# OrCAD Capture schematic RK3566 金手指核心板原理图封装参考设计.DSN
size A2; title: 野火_EBF RK3566 核心板; rev: V1.0; note: Connector; note: https://yehuosm.tmall.com
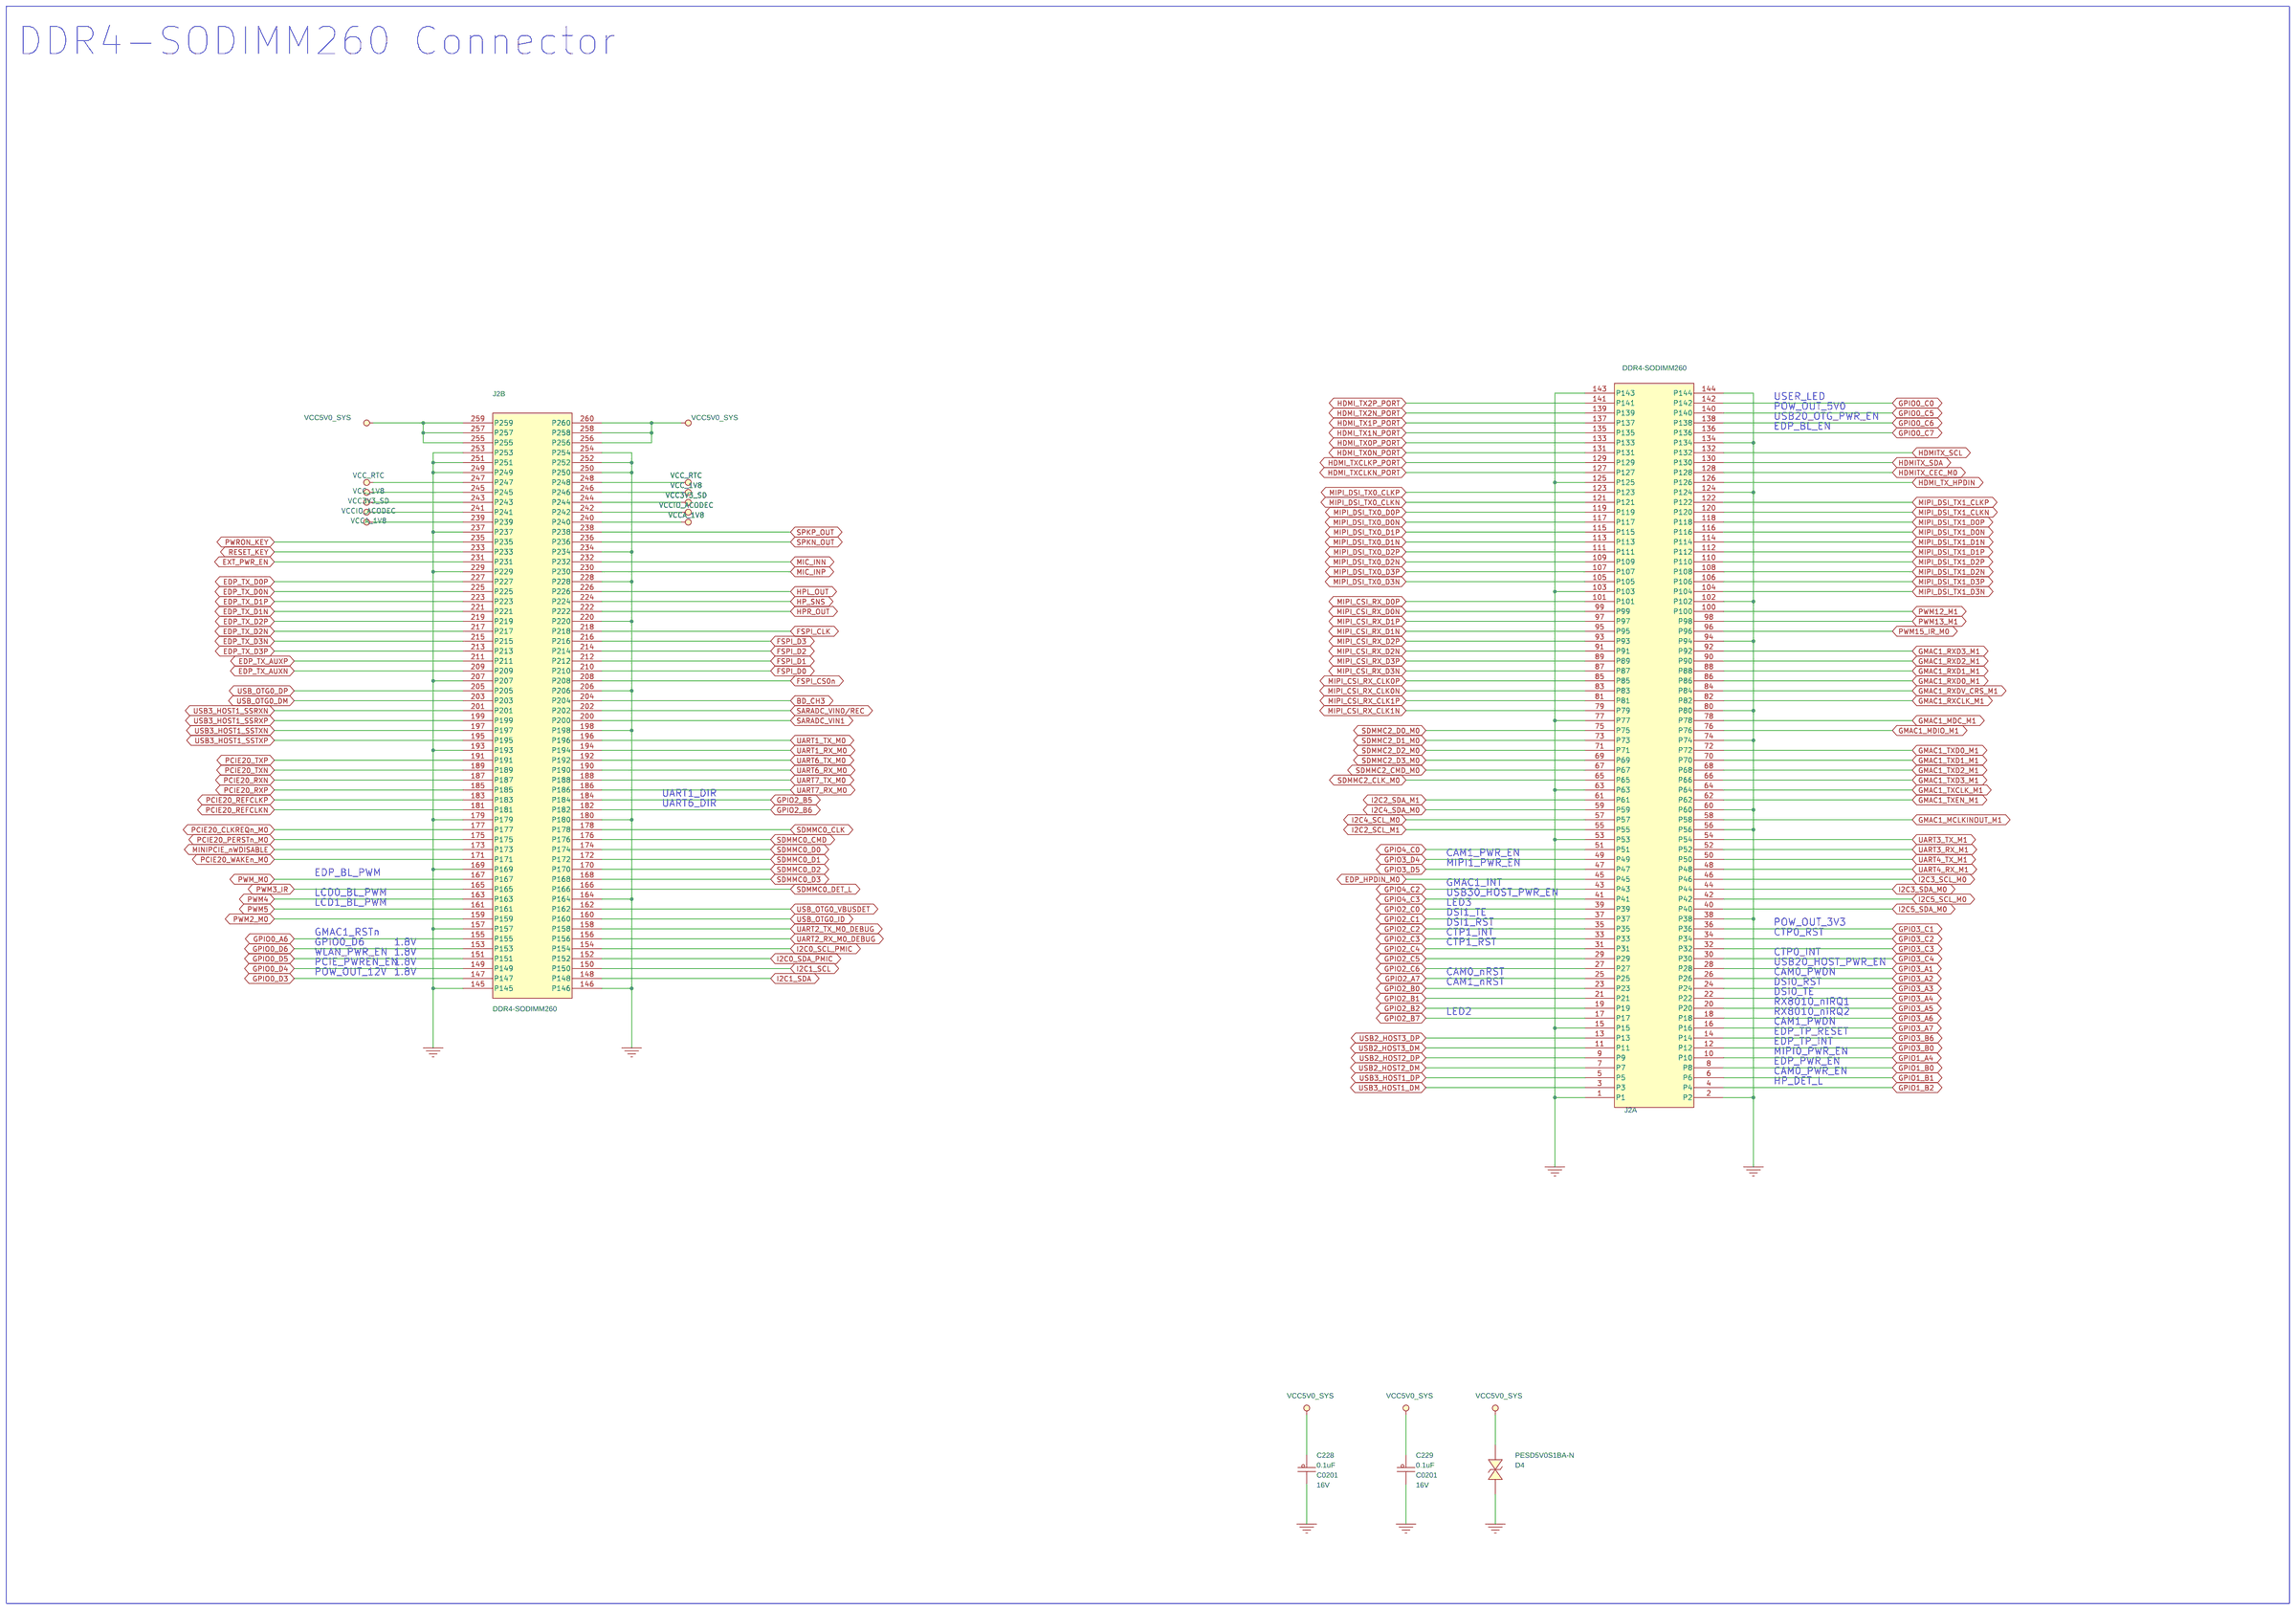
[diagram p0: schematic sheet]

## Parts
C228  0.1uF  [C0201]
C229  0.1uF  [C0201]
D4  PESD5V0S1BA-N  [sod323_CA]
J2  DDR4-SODIMM260  [SODIMMDDR4_260_0p5]  (sections A,B)

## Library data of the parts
C228 C229 = CAP_NP: Voltage: 16V; 规格: 贴片电容0.1uF 10% 16V X5R 0201; 规格编号: CL03A104KO3NNNC; 规格书: 三星电容.pdf; 价格: 0.006; 类别: 贴片电容0201; 品牌: 三星; 生命周期: 量产; 条码: EBF29060189
D4 = DIODE_BI-DIR_TRIG: 规格: 防静电保护ESD二极管 箝位电压21V 击穿电压6V 反向关断电压5V; 规格书: 伯恩半导体-PESD5V0S1BA-N.pdf; 价格: 0.196644; 类别: 贴片ESD; 品牌: 伯恩半导体; 生命周期: 量产; 条码: EBF29140021
J2 = DDR4-SODIMM260: 规格: 正装 DDR4 笔记本内存条 金手指 板框 260pin 间距0.5mm; 类别: 金手指连接器; 生命周期: 量产; 条码: EBF29040118

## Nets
GND: C228.2 C229.2 D4.1 J2.1(P1) J2.2(P2) J2.15(P15) J2.38(P38) J2.53(P53) J2.56(P56) J2.60(P60) J2.63(P63) J2.74(P74) J2.77(P77) J2.80(P80) J2.94(P94) J2.102(P102) J2.103(P103) J2.124(P124) J2.125(P125) J2.134(P134) J2.143(P143) J2.144(P144) J2.145(P145) J2.146(P146) J2.157(P157) J2.164(P164) J2.169(P169) J2.179(P179) J2.180(P180) J2.193(P193) J2.198(P198) J2.206(P206) J2.207(P207) J2.220(P220) J2.228(P228) J2.229(P229) J2.234(P234) J2.237(P237) J2.249(P249) J2.250(P250) J2.251(P251) J2.252(P252) J2.253(P253) J2.254(P254)
VCC3V3_SD: J2.243(P243) J2.244(P244)
VCC5V0_SYS: C228.1 C229.1 D4.2 J2.255(P255) J2.256(P256) J2.257(P257) J2.258(P258) J2.259(P259) J2.260(P260)
VCC_1V8: J2.245(P245) J2.246(P246)
VCC_RTC: J2.247(P247) J2.248(P248)
VCCA_1V8: J2.239(P239) J2.240(P240)
VCCIO_ACODEC: J2.241(P241) J2.242(P242)
BD_CH3: J2.204(P204)
EDP_HPDIN_M0: J2.45(P45)
EDP_TX_AUXN: J2.209(P209)
EDP_TX_AUXP: J2.211(P211)
EDP_TX_D0N: J2.225(P225)
EDP_TX_D0P: J2.227(P227)
EDP_TX_D1N: J2.221(P221)
EDP_TX_D1P: J2.223(P223)
EDP_TX_D2N: J2.217(P217)
EDP_TX_D2P: J2.219(P219)
EDP_TX_D3N: J2.215(P215)
EDP_TX_D3P: J2.213(P213)
EXT_PWR_EN: J2.231(P231)
FSPI_CLK: J2.218(P218)
FSPI_CS0n: J2.208(P208)
FSPI_D0: J2.210(P210)
FSPI_D1: J2.212(P212)
FSPI_D2: J2.214(P214)
FSPI_D3: J2.216(P216)
GMAC1_MCLKINOUT_M1: J2.58(P58)
GMAC1_MDC_M1: J2.78(P78)
GMAC1_MDIO_M1: J2.76(P76)
GMAC1_RXCLK_M1: J2.82(P82)
GMAC1_RXD0_M1: J2.86(P86)
GMAC1_RXD1_M1: J2.88(P88)
GMAC1_RXD2_M1: J2.90(P90)
GMAC1_RXD3_M1: J2.92(P92)
GMAC1_RXDV_CRS_M1: J2.84(P84)
GMAC1_TXCLK_M1: J2.64(P64)
GMAC1_TXD0_M1: J2.72(P72)
GMAC1_TXD1_M1: J2.70(P70)
GMAC1_TXD2_M1: J2.68(P68)
GMAC1_TXD3_M1: J2.66(P66)
GMAC1_TXEN_M1: J2.62(P62)
GPIO0_A6: J2.155(P155)
GPIO0_C0: J2.142(P142)
GPIO0_C5: J2.140(P140)
GPIO0_C6: J2.138(P138)
GPIO0_C7: J2.136(P136)
GPIO0_D3: J2.147(P147)
GPIO0_D4: J2.149(P149)
GPIO0_D5: J2.151(P151)
GPIO0_D6: J2.153(P153)
GPIO1_A4: J2.10(P10)
GPIO1_B0: J2.8(P8)
GPIO1_B1: J2.6(P6)
GPIO1_B2: J2.4(P4)
GPIO2_A7: J2.25(P25)
GPIO2_B0: J2.23(P23)
GPIO2_B1: J2.21(P21)
GPIO2_B2: J2.19(P19)
GPIO2_B5: J2.184(P184)
GPIO2_B6: J2.182(P182)
GPIO2_B7: J2.17(P17)
GPIO2_C0: J2.39(P39)
GPIO2_C1: J2.37(P37)
GPIO2_C2: J2.35(P35)
GPIO2_C3: J2.33(P33)
GPIO2_C4: J2.31(P31)
GPIO2_C5: J2.29(P29)
GPIO2_C6: J2.27(P27)
GPIO3_A1: J2.28(P28)
GPIO3_A2: J2.26(P26)
GPIO3_A3: J2.24(P24)
GPIO3_A4: J2.22(P22)
GPIO3_A5: J2.20(P20)
GPIO3_A6: J2.18(P18)
GPIO3_A7: J2.16(P16)
GPIO3_B0: J2.12(P12)
GPIO3_B6: J2.14(P14)
GPIO3_C1: J2.36(P36)
GPIO3_C2: J2.34(P34)
GPIO3_C3: J2.32(P32)
GPIO3_C4: J2.30(P30)
GPIO3_D4: J2.49(P49)
GPIO3_D5: J2.47(P47)
GPIO4_C0: J2.51(P51)
GPIO4_C2: J2.43(P43)
GPIO4_C3: J2.41(P41)
HDMI_TX0N_PORT: J2.131(P131)
HDMI_TX0P_PORT: J2.133(P133)
HDMI_TX1N_PORT: J2.135(P135)
HDMI_TX1P_PORT: J2.137(P137)
HDMI_TX2N_PORT: J2.139(P139)
HDMI_TX2P_PORT: J2.141(P141)
HDMI_TX_HPDIN: J2.126(P126)
HDMI_TXCLKN_PORT: J2.127(P127)
HDMI_TXCLKP_PORT: J2.129(P129)
HDMITX_CEC_M0: J2.128(P128)
HDMITX_SCL: J2.132(P132)
HDMITX_SDA: J2.130(P130)
HP_SNS: J2.224(P224)
HPL_OUT: J2.226(P226)
HPR_OUT: J2.222(P222)
I2C0_SCL_PMIC: J2.154(P154)
I2C0_SDA_PMIC: J2.152(P152)
I2C1_SCL: J2.150(P150)
I2C1_SDA: J2.148(P148)
I2C2_SCL_M1: J2.55(P55)
I2C2_SDA_M1: J2.61(P61)
I2C3_SCL_M0: J2.46(P46)
I2C3_SDA_M0: J2.44(P44)
I2C4_SCL_M0: J2.57(P57)
I2C4_SDA_M0: J2.59(P59)
I2C5_SCL_M0: J2.42(P42)
I2C5_SDA_M0: J2.40(P40)
MIC_INN: J2.232(P232)
MIC_INP: J2.230(P230)
MINIPCIE_nWDISABLE: J2.173(P173)
MIPI_CSI_RX_CLK0N: J2.83(P83)
MIPI_CSI_RX_CLK0P: J2.85(P85)
MIPI_CSI_RX_CLK1N: J2.79(P79)
MIPI_CSI_RX_CLK1P: J2.81(P81)
MIPI_CSI_RX_D0N: J2.99(P99)
MIPI_CSI_RX_D0P: J2.101(P101)
MIPI_CSI_RX_D1N: J2.95(P95)
MIPI_CSI_RX_D1P: J2.97(P97)
MIPI_CSI_RX_D2N: J2.91(P91)
MIPI_CSI_RX_D2P: J2.93(P93)
MIPI_CSI_RX_D3N: J2.87(P87)
MIPI_CSI_RX_D3P: J2.89(P89)
MIPI_DSI_TX0_CLKN: J2.121(P121)
MIPI_DSI_TX0_CLKP: J2.123(P123)
MIPI_DSI_TX0_D0N: J2.117(P117)
MIPI_DSI_TX0_D0P: J2.119(P119)
MIPI_DSI_TX0_D1N: J2.113(P113)
MIPI_DSI_TX0_D1P: J2.115(P115)
MIPI_DSI_TX0_D2N: J2.109(P109)
MIPI_DSI_TX0_D2P: J2.111(P111)
MIPI_DSI_TX0_D3N: J2.105(P105)
MIPI_DSI_TX0_D3P: J2.107(P107)
MIPI_DSI_TX1_CLKN: J2.120(P120)
MIPI_DSI_TX1_CLKP: J2.122(P122)
MIPI_DSI_TX1_D0N: J2.116(P116)
MIPI_DSI_TX1_D0P: J2.118(P118)
MIPI_DSI_TX1_D1N: J2.114(P114)
MIPI_DSI_TX1_D1P: J2.112(P112)
MIPI_DSI_TX1_D2N: J2.108(P108)
MIPI_DSI_TX1_D2P: J2.110(P110)
MIPI_DSI_TX1_D3N: J2.104(P104)
MIPI_DSI_TX1_D3P: J2.106(P106)
PCIE20_CLKREQn_M0: J2.177(P177)
PCIE20_PERSTn_M0: J2.175(P175)
PCIE20_REFCLKN: J2.181(P181)
PCIE20_REFCLKP: J2.183(P183)
PCIE20_RXN: J2.187(P187)
PCIE20_RXP: J2.185(P185)
PCIE20_TXN: J2.189(P189)
PCIE20_TXP: J2.191(P191)
PCIE20_WAKEn_M0: J2.171(P171)
PWM2_M0: J2.159(P159)
PWM3_IR: J2.165(P165)
PWM4: J2.163(P163)
PWM5: J2.161(P161)
PWM12_M1: J2.100(P100)
PWM13_M1: J2.98(P98)
PWM15_IR_M0: J2.96(P96)
PWM_M0: J2.167(P167)
PWRON_KEY: J2.235(P235)
RESET_KEY: J2.233(P233)
SARADC_VIN0/REC: J2.202(P202)
SARADC_VIN1: J2.200(P200)
SDMMC0_CLK: J2.178(P178)
SDMMC0_CMD: J2.176(P176)
SDMMC0_D0: J2.174(P174)
SDMMC0_D1: J2.172(P172)
SDMMC0_D2: J2.170(P170)
SDMMC0_D3: J2.168(P168)
SDMMC0_DET_L: J2.166(P166)
SDMMC2_CLK_M0: J2.65(P65)
SDMMC2_CMD_M0: J2.67(P67)
SDMMC2_D0_M0: J2.75(P75)
SDMMC2_D1_M0: J2.73(P73)
SDMMC2_D2_M0: J2.71(P71)
SDMMC2_D3_M0: J2.69(P69)
SPKN_OUT: J2.236(P236)
SPKP_OUT: J2.238(P238)
UART1_RX_M0: J2.194(P194)
UART1_TX_M0: J2.196(P196)
UART2_RX_M0_DEBUG: J2.156(P156)
UART2_TX_M0_DEBUG: J2.158(P158)
UART3_RX_M1: J2.52(P52)
UART3_TX_M1: J2.54(P54)
UART4_RX_M1: J2.48(P48)
UART4_TX_M1: J2.50(P50)
UART6_RX_M0: J2.190(P190)
UART6_TX_M0: J2.192(P192)
UART7_RX_M0: J2.186(P186)
UART7_TX_M0: J2.188(P188)
USB2_HOST2_DM: J2.7(P7)
USB2_HOST2_DP: J2.9(P9)
USB2_HOST3_DM: J2.11(P11)
USB2_HOST3_DP: J2.13(P13)
USB3_HOST1_DM: J2.3(P3)
USB3_HOST1_DP: J2.5(P5)
USB3_HOST1_SSRXN: J2.201(P201)
USB3_HOST1_SSRXP: J2.199(P199)
USB3_HOST1_SSTXN: J2.197(P197)
USB3_HOST1_SSTXP: J2.195(P195)
USB_OTG0_DM: J2.203(P203)
USB_OTG0_DP: J2.205(P205)
USB_OTG0_ID: J2.160(P160)
USB_OTG0_VBUSDET: J2.162(P162)

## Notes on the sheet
- DDR4-SODIMM260 Connector
- USER_LED
- POW_OUT_5V0
- USB20_OTG_PWR_EN
- EDP_BL_EN
- UART1_DIR
- UART6_DIR
- CAM1_PWR_EN
- MIPI1_PWR_EN
- EDP_BL_PWM
- LCD0_BL_PWM
- GMAC1_INT
- USB30_HOST_PWR_EN
- LCD1_BL_PWM
- LED3
- DSI1_TE
- DSI1_RST
- POW_OUT_3V3
- GMAC1_RSTn
- CTP1_INT
- CTP0_RST
- GPIO0_D6
- 1.8V
- CTP1_RST
- PCIE_PWREN_EN
- WLAN_PWR_EN
- 1.8V
- 1.8V
- CTP0_INT
- USB20_HOST_PWR_EN
- POW_OUT_12V
- 1.8V
- CAM0_nRST
- CAM0_PWDN
- CAM1_nRST
- DSI0_RST
- DSI0_TE
- RX8010_nIRQ1
- LED2
- CAM1_PWDN
- RX8010_nIRQ2
- EDP_TP_RESET
- EDP_TP_INT
- MIPI0_PWR_EN
- EDP_PWR_EN
- CAM0_PWR_EN
- HP_DET_L
